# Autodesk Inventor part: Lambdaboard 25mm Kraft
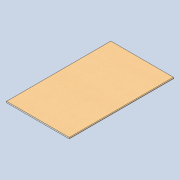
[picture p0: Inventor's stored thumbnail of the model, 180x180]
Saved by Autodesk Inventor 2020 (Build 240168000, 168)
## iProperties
Created: 2020-11
Part Number: Lambdaboard 25mm Kraft
Material: Generic
Document SubType Name: Modeling
Designer: Yolande
Density: 1 g/cm^3
Appearance: Default
Author: Yolande
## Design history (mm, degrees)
sketch "Sketch1"
  geometry: L1 (10, 0)-(1210, 0); L2 (1220, 10)-(1220, 15); L3 (1210, 25)-(10, 25); L4 (0, 15)-(0, 10); A1 r 10 centre (10, 15) between (10, 25) and (0, 15); A2 r 10 centre (10, 10) between (0, 10) and (10, 0); A3 r 10 centre (1210, 15) between (1220, 15) and (1210, 25); A4 r 10 centre (1210, 10) between (1210, 0) and (1220, 10); 3 further points
  constraints: 8 end point, 8 point on circle, 8 tangent, 6 point on line, 4 centre point, 3 equal radius, 3 perpendicular, 1 horizontal
  dimensions: "d0" = 1220 distance of point (0, 0) point (1220, 0); "d1" = 25 distance of point (1220, 0) point (1220, 25); "d2" = 10 radius of A1
extrude "Extrusion1" new body sketch "Sketch1" distance "d3" = 2000; taper "d4" = 0 deg
body "Solid1"
